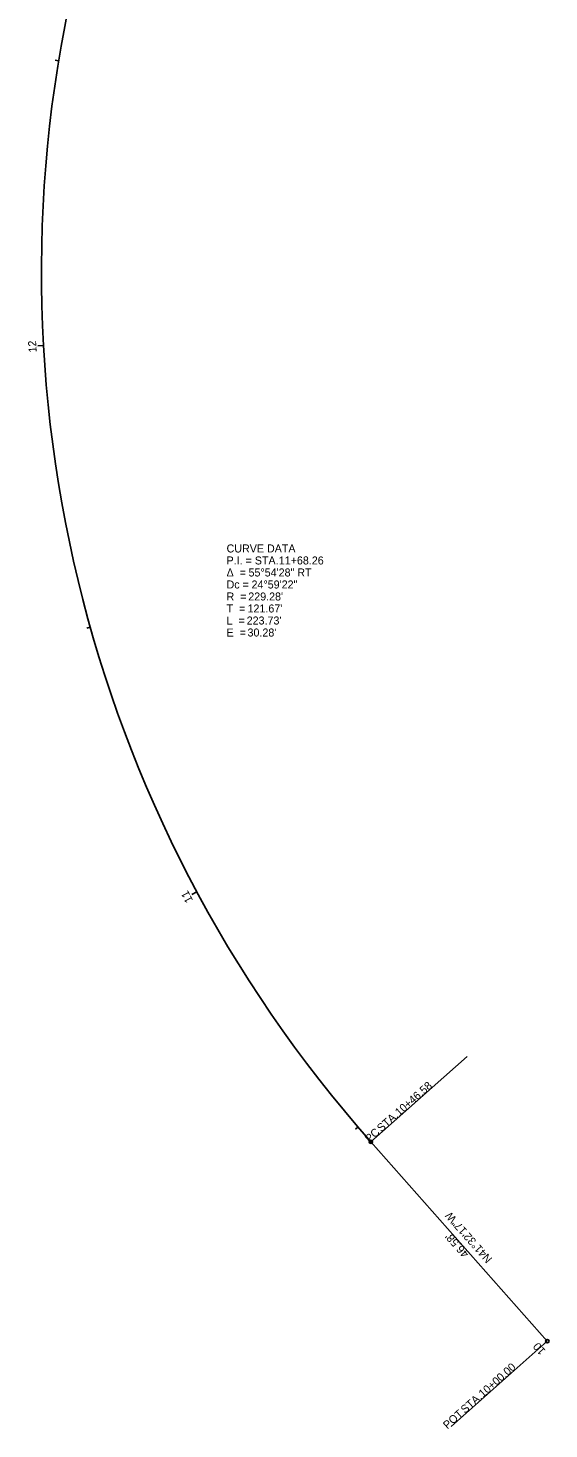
# Model space of a CAD drawing. Extents: x 2296330 to 2296526, y 654819 to 655309.
# Drawn here: x 2296408.7 to 2296499.9, y 654819.1 to 655064.1 of the extents above; entities that cross this region are included whole.
import ezdxf

# ---------------------------------------------------------------- set-up
doc = ezdxf.new("R2010")
doc.units = 0
for name, color, linetype in [('GE_P_Alignment', 7, 'Continuous'), ('GE_P_Alignment_100_Bearings', 7, 'Continuous'), ('GE_P_Alignment_100_Cardinal_Points', 7, 'Continuous'), ('GE_P_Alignment_100_Curve_Data', 7, 'Continuous'), ('GE_P_Alignment_100_Distances', 7, 'Continuous'), ('GE_P_Alignment_100_Stations', 7, 'Continuous')]:
    doc.layers.add(name, color=color, linetype=linetype)

msp = doc.modelspace()

# ---------------------------------------------------------------- linework, layer by layer
at = {"layer": 'GE_P_Alignment'}
msp.add_line((2296499.64, 654834.41), (2296468.75, 654869.28), dxfattribs=at)
msp.add_line((2296499.64, 654834.41), (2296468.75, 654869.28), dxfattribs=at)
msp.add_arc((2296640.37, 655021.32), 229.28, 165.6301, 221.5381, dxfattribs=at)
msp.add_arc((2296640.37, 655021.32), 229.28, 165.6301, 221.5381, dxfattribs=at)
at = {"layer": 'GE_P_Alignment_100_Cardinal_Points'}
for p, q in [((2296468.75, 654869.28), (2296485.59, 654884.2)), ((2296499.64, 654834.41), (2296482.8, 654819.49))]:
    msp.add_line(p, q, dxfattribs=at)
for centre in [(2296468.75, 654869.28), (2296499.64, 654834.41)]:
    msp.add_circle(centre, 0.3, dxfattribs=at)
at = {"layer": 'GE_P_Alignment_100_Stations'}
for p, q in [((2296414.1, 655058.35), (2296413.51, 655058.45)), ((2296411.44, 655008.52), (2296410.45, 655008.46)), ((2296419.64, 654959.3), (2296419.06, 654959.13)), ((2296438.28, 654913.01), (2296437.4, 654912.54)), ((2296466.5, 654871.85), (2296466.05, 654871.46)), ((2296499.64, 654834.41), (2296498.89, 654833.75))]:
    msp.add_line(p, q, dxfattribs=at)

# ---------------------------------------------------------------- texts
at = {"layer": 'GE_P_Alignment_100_Bearings'}
msp.add_text('N41°32\'17"W', height=1.4, rotation=131.5381, dxfattribs=at).set_placement((2296490.07, 654848.83))
at = {"layer": 'GE_P_Alignment_100_Cardinal_Points'}
for s, p in [('10+46.58', (2296473.73, 654873.69)), (' STA. ', (2296470.19, 654870.56)), ('PC', (2296468.48, 654869.04)), ('10+00.00', (2296488.38, 654824.47)), (' STA. ', (2296484.85, 654821.34)), ('POT', (2296482.15, 654818.95))]:
    msp.add_text(s, height=1.4, rotation=41.5381, dxfattribs=at).set_placement(p)
at = {"layer": 'GE_P_Alignment_100_Curve_Data'}
for s, p in [('CURVE DATA', (2296443.5, 654972.35)), ('P.I. = STA. ', (2296443.5, 654970.25)), ('11+68.26', (2296452.64, 654970.25)), ('Δ  = ', (2296443.5, 654968.15)), ('55°54\'28" RT', (2296447.34, 654968.15)), ('Dc = ', (2296443.5, 654966.05)), ('24°59\'22"', (2296447.87, 654966.05)), ('T  = ', (2296443.5, 654961.85)), ('R  = ', (2296443.5, 654963.95)), ("121.67'", (2296447.17, 654961.85)), ("229.28'", (2296447.3, 654963.95)), ('L  = ', (2296443.5, 654959.75)), ("223.73'", (2296447.02, 654959.75)), ('E  = ', (2296443.5, 654957.65)), ("30.28'", (2296447.17, 654957.65))]:
    msp.add_text(s, height=1.4, dxfattribs=at).set_placement(p)
at = {"layer": 'GE_P_Alignment_100_Distances'}
msp.add_text("46.58'", height=1.4, rotation=131.5381, dxfattribs=at).set_placement((2296486.02, 654849.75))
at = {"layer": 'GE_P_Alignment_100_Stations'}
for s, rotation, p in [('12', 93.2, (2296410.26, 655007.37)), ('11', 118.1894, (2296437.66, 654911.52)), ('10', 131.5381, (2296499.44, 654832.75))]:
    msp.add_text(s, height=1.4, rotation=rotation, dxfattribs=at).set_placement(p)

doc.saveas('drawing.dxf')
